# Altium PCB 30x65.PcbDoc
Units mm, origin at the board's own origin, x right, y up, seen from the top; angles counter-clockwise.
Board outline 65 x 35 mm, 4 copper layers (Top Layer, Internal Plane 1, Internal Plane 2, Bottom Layer); 12 components, 14 nets, 22 pads, 0 vias.
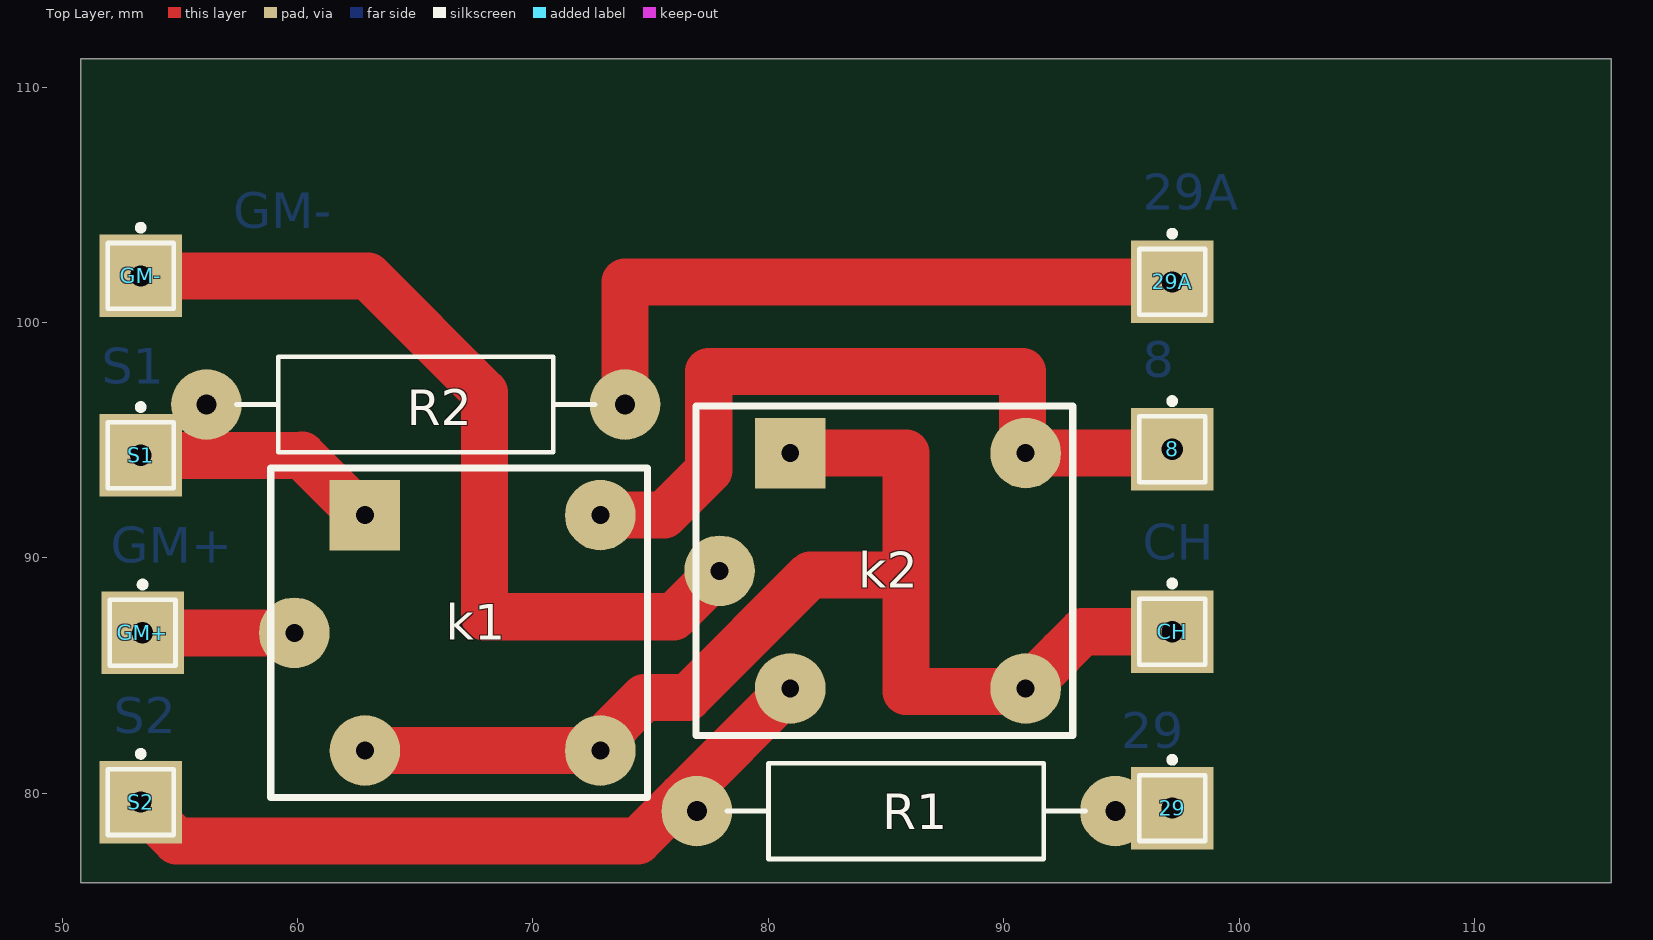
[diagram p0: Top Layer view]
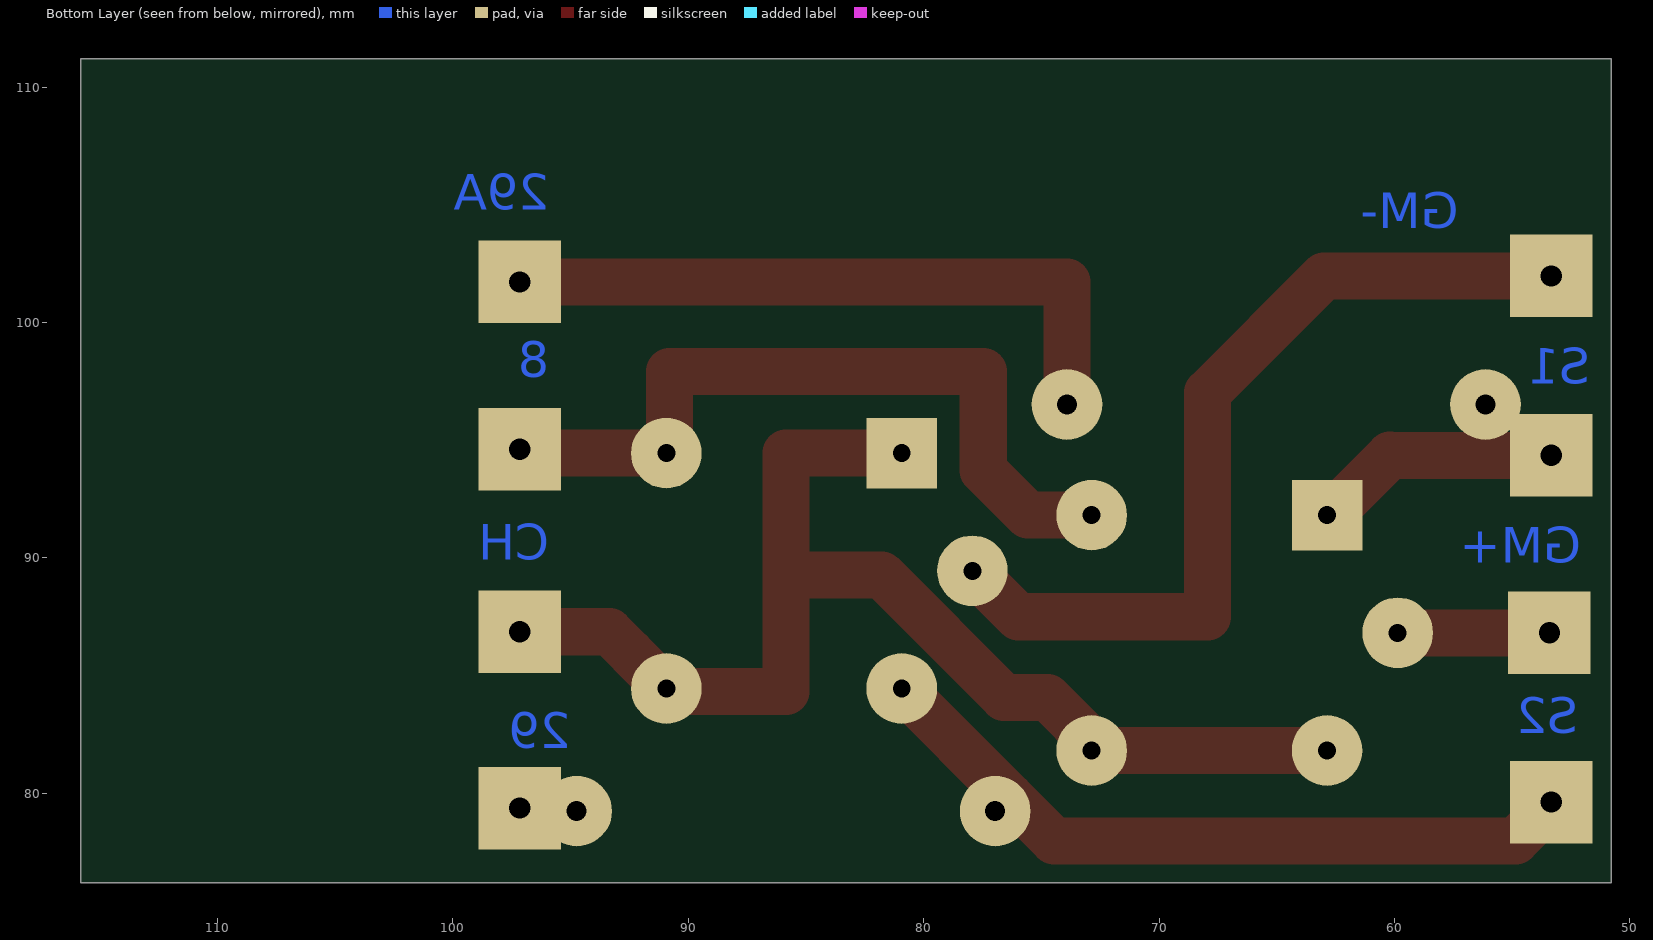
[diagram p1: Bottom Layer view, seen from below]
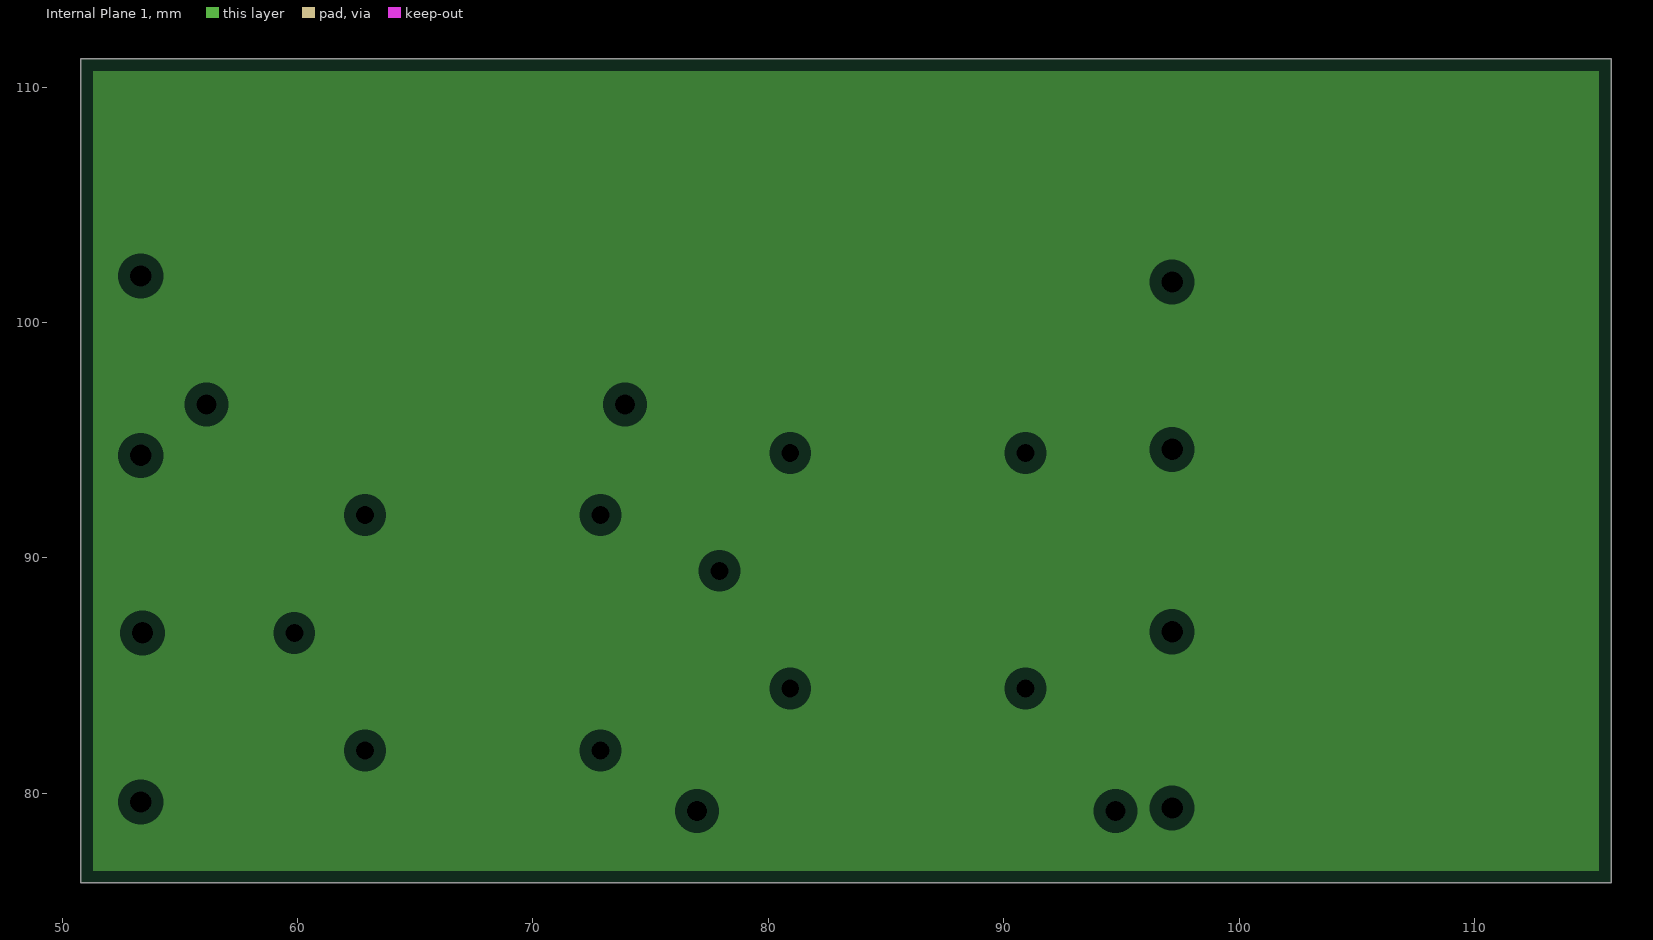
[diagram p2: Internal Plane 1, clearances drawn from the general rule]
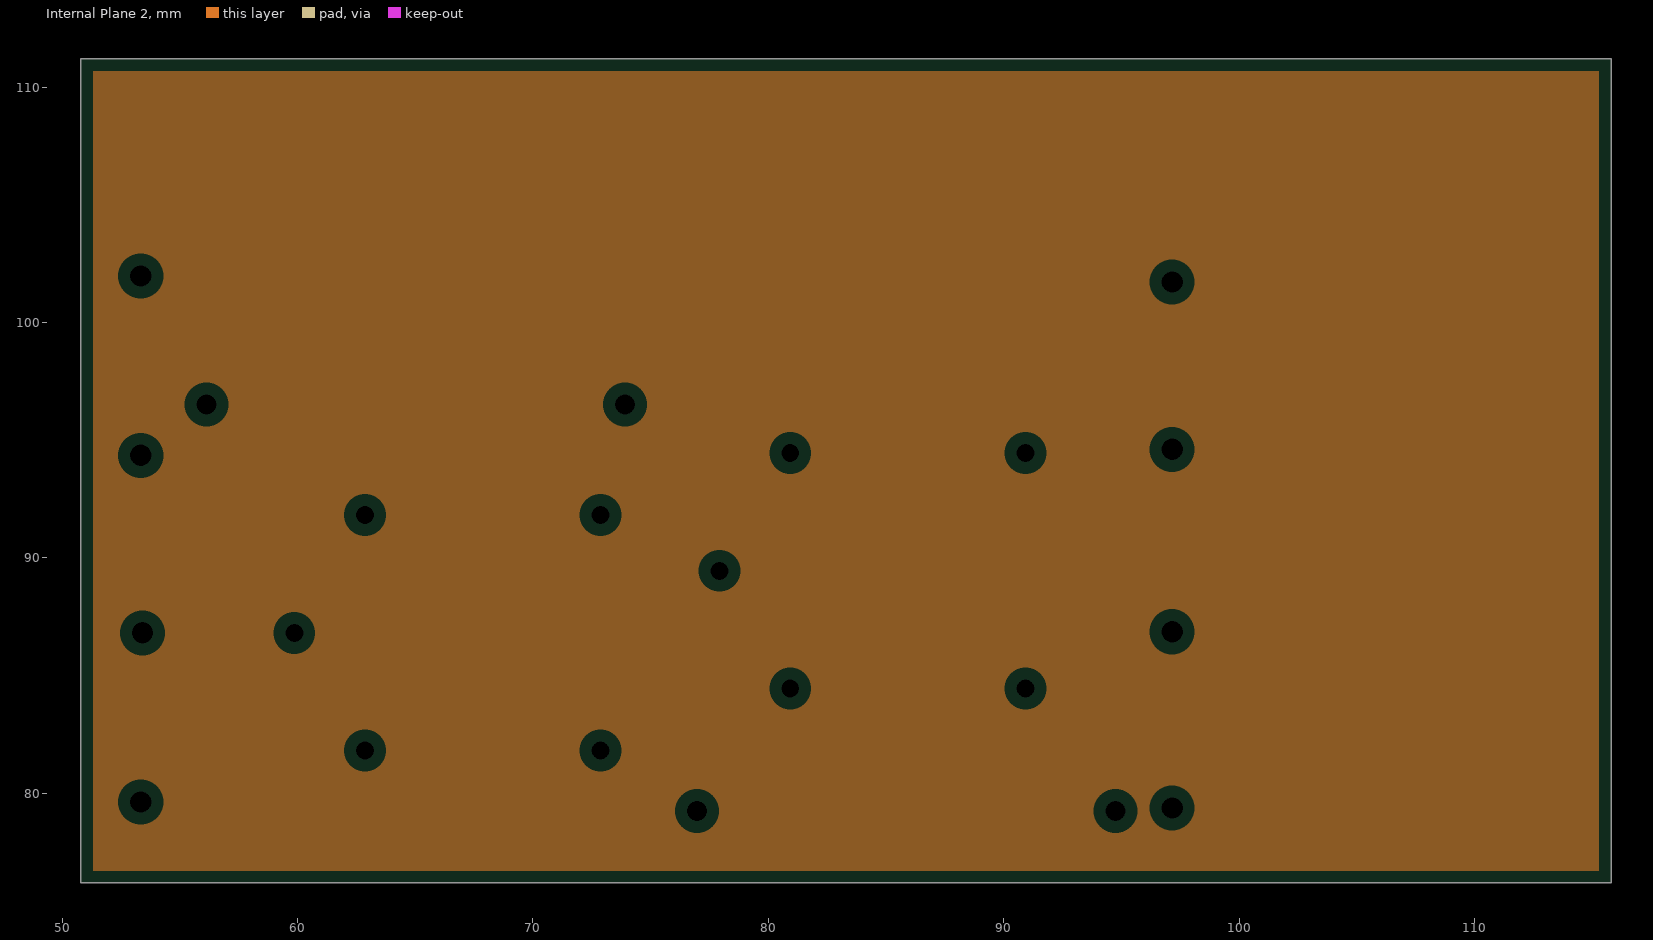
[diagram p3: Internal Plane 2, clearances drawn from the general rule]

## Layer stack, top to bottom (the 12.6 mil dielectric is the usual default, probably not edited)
Top Layer: signal copper 0.0356
Dielectric: dielectric 0.32, FR-4, Dk 4.8
Internal Plane 1: plane copper 0.0356
Dielectric: dielectric 0.32, FR-4, Dk 4.8
Internal Plane 2: plane copper 0.0356
Dielectric: dielectric 0.32, FR-4, Dk 4.8
Bottom Layer: signal copper 0.0356

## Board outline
50.8,76.2 115.8,76.2 115.8,111.2 50.8,111.2

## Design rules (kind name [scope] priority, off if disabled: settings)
Clearance [All] p1: gap=0.2
PlaneClearance [All] p1: clearance=0.508
PlaneConnect [All] p1: planeconnectstyle=Relief reliefexpansion=0.508 reliefentries=4 reliefconductorwidth=0.254 reliefairgap=0.254
PolygonConnect [All] p1: connectstyle=Relief reliefconductorwidth=0.254 reliefentries=4 polygonreliefangle="90 Angle"
RoutingVias [All] p1: holewidth=0.6 width=1 viastyle="Through Hole" minholewidth=0.711 minwidth=1.27 maxholewidth=0.711 maxwidth=1.27
SolderMaskExpansion [All] p1: expansion=0.102
TestPointUsage [All] p1: valid=0 allowmultiple=FALSE
Testpoint [All] p1: side=15 testpointundercomponent=TRUE minsize=1.016 maxsize=2.54 preferedsize=1.524 minholesize=0 maxholesize=1.016 preferedholesize=0.813 testpointgrid=0.025 style=1023 order=0123456789
Width [All] p1: maxlimit=4 minlimit=2 preferedwidth=1.5 toplayer_prefwidth=2 bottomlayer_prefwidth=2 minimp=50.000000 maximp=50.000000 favimp=50.000000
17 further rules are at their usual default settings.

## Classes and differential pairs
component class 30x65: 8 29 29A CH GM+ GM- S1

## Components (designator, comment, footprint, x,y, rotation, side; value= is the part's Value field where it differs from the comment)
8 "8" PIN1 97.155,94.615 r0 top (schematic designator P3)
29 "29" PIN1 97.155,79.375 r0 top (schematic designator P2)
29A "29A" PIN1 97.155,101.727 r0 top (schematic designator P1)
CH "CH" PIN1 97.155,86.868 r0 top (schematic designator P4)
GM+ "Motor" PIN1 53.421,86.821 r0 top (schematic designator P5)
GM- "Motor" PIN1 53.34,101.981 r0 top (schematic designator P6)
k1 "Component_1" PCBComponent_1 55.865,78.821 r0 top
k2 "Component_1" PCBComponent_1 73.932,81.455 r0 top
R1 "Res2" AXIAL-0.7 85.852,79.248 r180 top
R2 "Res2" AXIAL-0.7 65.024,96.52 r180 top
S1 "S1" PIN1 53.34,94.361 r0 top (schematic designator P7)
S2 "S2" PIN1 53.34,79.629 r0 top (schematic designator P8)

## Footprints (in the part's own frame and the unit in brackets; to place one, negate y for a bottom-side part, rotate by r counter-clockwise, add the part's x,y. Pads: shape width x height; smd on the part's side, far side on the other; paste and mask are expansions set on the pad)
AXIAL-0.7 [mm] "Variable Resistor; 2 Leads"
  round 3 hole 0.85: 1(-8.89,0) 2(8.89,0)
  silkscreen extent -7.62,-2.03 7.62,2.03
PCBComponent_1 [mm]
  rect 3x3 hole 0.762: 1(7,13)
  round 3 hole 0.762: 2(7,3) 3(4,8) 4(17,13) 5(17,3)
  silkscreen extent 3,1 19,15, body extent 3,1 19,15, height 12.5
PIN1 [mm] "Connector; Plug"
  rect 3.5x3.5 hole 0.9: 1(0,0)
  silkscreen extent -1.4,-1.4 1.4,2.17

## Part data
8 29 29A CH GM+ GM- S1 S2: library part Plug, "Plug"
R1 R2: "Resistor"

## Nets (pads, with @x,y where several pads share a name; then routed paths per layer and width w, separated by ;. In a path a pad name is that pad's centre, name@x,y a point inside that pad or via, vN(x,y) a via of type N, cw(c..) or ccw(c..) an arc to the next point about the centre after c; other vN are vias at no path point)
8: 8.1 k1.4 k2.4 | length 33.6
  Top Layer w2: k1.4@72.484,91.821 k1.4 75.565,91.821 77.47,93.726 77.47,97.917 90.805,97.917 k2.4@90.805,94.582 ; k2.4 96.995,94.455 8.1 8.1@97.79,94.615
29A: 29A.1 R2.1 | length 28.6
  Top Layer w2: R2.1@74.168,96.52 74.041,96.647 73.914,96.774 73.914,101.727 29A.1
CH: CH.1 k1.2 k1.5 k2.1 k2.5 | length 56
  Top Layer w2: k1.2 k1.5@72.484,81.821 ; k1.5 k1.5@72.484,81.821 ; k2.1 85.852,94.455 85.852,89.281 ; k2.5@90.932,84.328 85.852,84.328 85.852,89.281 ; 92.456,85.979 k2.5 93.345,86.868 CH.1 ; k1.5@72.484,81.821 72.674,82.011 74.737,84.074 76.581,84.074 81.788,89.281 85.852,89.281
GM1: GM+.1 k1.3 | length 6.4
  Top Layer w2: GM+.1 k1.3
GM2: GM-.1 k2.3 | length 37
  Top Layer w2: GM-.1 62.992,101.981 67.945,97.028 67.945,87.503 75.98,87.503 k2.3
Net29A_1: 29.1 R1.1 | length 2.8
  Top Layer w2: R1.1@94.361,79.375 94.742,79.375 29.1
Netk1_1: k1.1 R2.2 S1.1 | length 10.6
  Top Layer w2: S1.1 56.134,94.361 60.178,94.361 60.188,94.371 62.738,91.821 k1.1
Netk1_3: 
Netk1_4: 
Netk2_2: k2.2 R1.2 S2.1 | length 40.1
  Top Layer w2: S2.1@53.213,79.629 53.276,79.566 54.864,77.978 65.405,77.978 ; k2.2 76.343,79.866 74.455,77.978 ; 65.405,77.978 74.455,77.978 ; 65.405,77.978 74.455,77.978
Netk2_3: 
NetP1_1: 
NetP2_1: 
S1: 

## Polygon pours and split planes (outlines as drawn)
no net on Internal Plane 1 (split plane): 115.29,76.71 51.31,76.71 51.31,110.69 115.29,110.69
no net on Internal Plane 2 (split plane): 115.29,76.71 51.31,76.71 51.31,110.69 115.29,110.69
